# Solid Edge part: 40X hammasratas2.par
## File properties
Author: Türk
Template: Iso Part.par
Last saved by: Türk
Revision: 8
Application: Solid Edge
Accuracy: 0,990
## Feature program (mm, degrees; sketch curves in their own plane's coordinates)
pattern "PatternOccurrence_1"  XOffset = 9 deg
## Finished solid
Body 1: solid body, 166 faces, 484 edges, 320 vertices.
  Faces by surface: plane 124, cylinder 42
  Edges by curve: line 400, circle 84
Bounding box of the edges (mm): 52.000 x 140.000 x 52.000, from (-26, 0, -26) to (26, 140, 26).
Cylindrical faces by radius (mm): R6 x2, R24 x40
Planar faces by outward normal: +x 1, +y 2, +z 1, -x 1, -y 2, -z 1, oblique 116
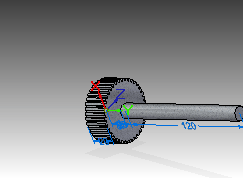
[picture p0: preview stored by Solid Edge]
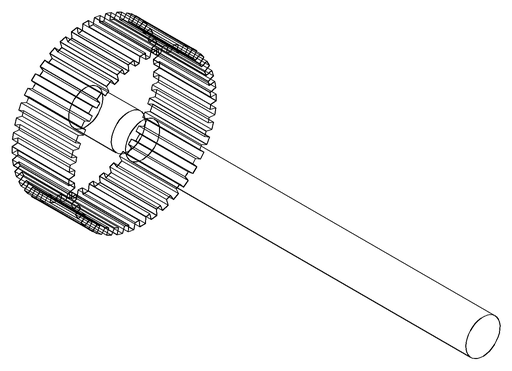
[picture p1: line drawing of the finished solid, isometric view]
